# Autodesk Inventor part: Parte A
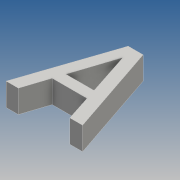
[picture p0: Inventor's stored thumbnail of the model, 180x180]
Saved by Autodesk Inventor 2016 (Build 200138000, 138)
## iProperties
Created: 2015-08
Part Number: Parte A
Material: Generic
Document SubType Name: Modeling
Designer: julian.chica
Density: 1 g/cm^3
Appearance: Default
Author: julian.chica
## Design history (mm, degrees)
sketch "Sketch1"
  geometry: L1 (-8.338, 20.108)-(8.338, 20.108); L2 (8.338, 20.108)-(8.338, 0); L3 (8.338, 0)-(-8.338, 0); L4 (-8.338, 0)-(-8.338, 20.108); 2 further points
  constraints: 1 coincident, 1 midpoint, 2 other
extrude "Extrusion1" new body sketch "Sketch1" distance "d1" = 5; taper "d2" = 0 deg
body "Solid1"
